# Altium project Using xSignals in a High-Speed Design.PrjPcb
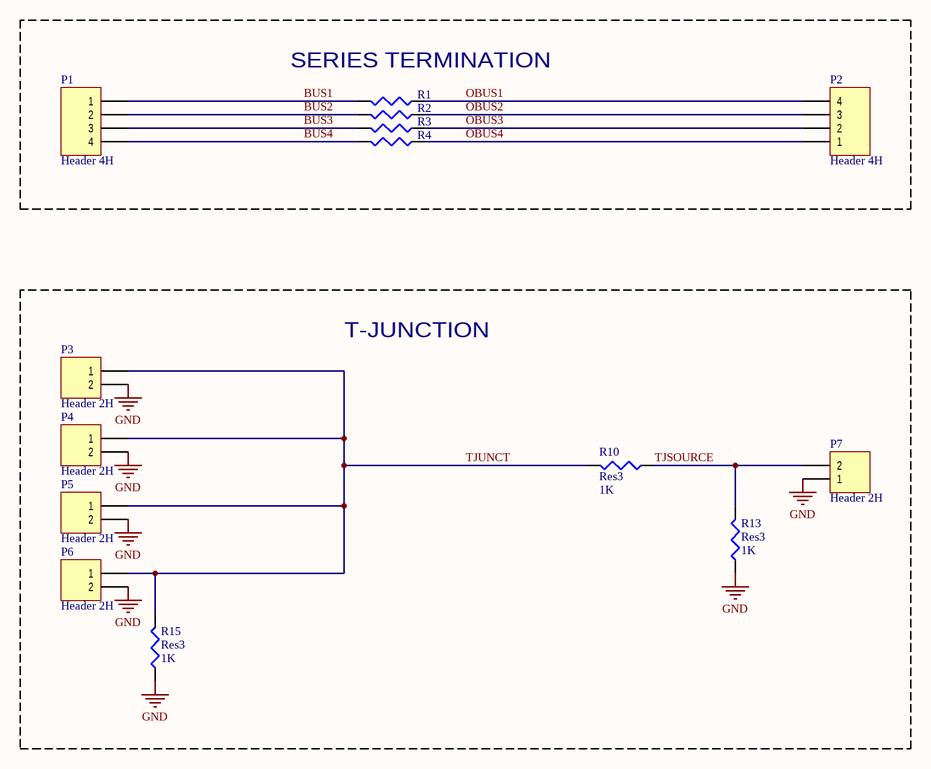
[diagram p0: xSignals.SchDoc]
1 sheet, 14 parts. Net scope: global (net labels, ports and power ports of the same name join across sheets).
Board files: xSignals Wizard.PcbDoc, Altium Advanced Training - xSignals - TJunction Completed.PcbDoc, Altium Advanced Training - xSignals - Series-Term Completed 2.PcbDoc, Altium Advanced Training - xSignals - Series-Term Completed.PcbDoc, Altium Advanced Training - xSignals completed.PcbDoc, xSignals.PcbDoc

## Sheet xSignals.SchDoc: Using xSignals in a High-Speed Design
size 431 x 279 mm; Organization: ORGANIZATION; Address1: ADDRESS 1; Address2: ADDRESS 2; Address3: ADDRESS 3; Address4: ADDRESS 4; Revision: -; ENG_APP_DATE: --/--/--; DSN_APP_DATE: --/--/--; CHK_APP_DATE: --/--/--

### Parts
P1  Header 4H  [HDR1X4H]
P2  Header 4H  [HDR1X4H]
P3  Header 2H  [HDR1X2H]
P4  Header 2H  [HDR1X2H]
P5  Header 2H  [HDR1X2H]
P6  Header 2H  [HDR1X2H]
P7  Header 2H  [HDR1X2H]
R1  Res3  [J1-0603]  (value not drawn)
R2  Res3  [J1-0603]  (value not drawn)
R3  Res3  [J1-0603]  (value not drawn)
R4  Res3  [J1-0603]  (value not drawn)
R10  Res3  value 1K  [J1-0603]
R13  Res3  value 1K  [J1-0603]
R15  Res3  value 1K  [J1-0603]

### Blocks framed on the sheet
SERIES TERMINATION: P1 P2 R1-R4
T-JUNCTION: P3-P7 R10 R13 R15

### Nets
GND: P3.2 P4.2 P5.2 P6.2 P7.1 R13.1 R15.1
BUS1: P1.1 R1.2
BUS2: P1.2 R2.2
BUS3: P1.3 R3.2
BUS4: P1.4 R4.2
OBUS1: P2.4 R1.1
OBUS2: P2.3 R2.1
OBUS3: P2.2 R3.1
OBUS4: P2.1 R4.1
TJSOURCE: P7.2 R10.1 R13.2
TJUNCT: P3.1 P4.1 P5.1 P6.1 R10.2 R15.2

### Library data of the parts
P1 P2 = Header 4H: Header, 4-Pin, Right Angle
P3-P7 = Header 2H: Header, 2-Pin, Right Angle
R1-R4 = Res3: Resistor; Value: 1K
R10 R13 R15 = Res3: Resistor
